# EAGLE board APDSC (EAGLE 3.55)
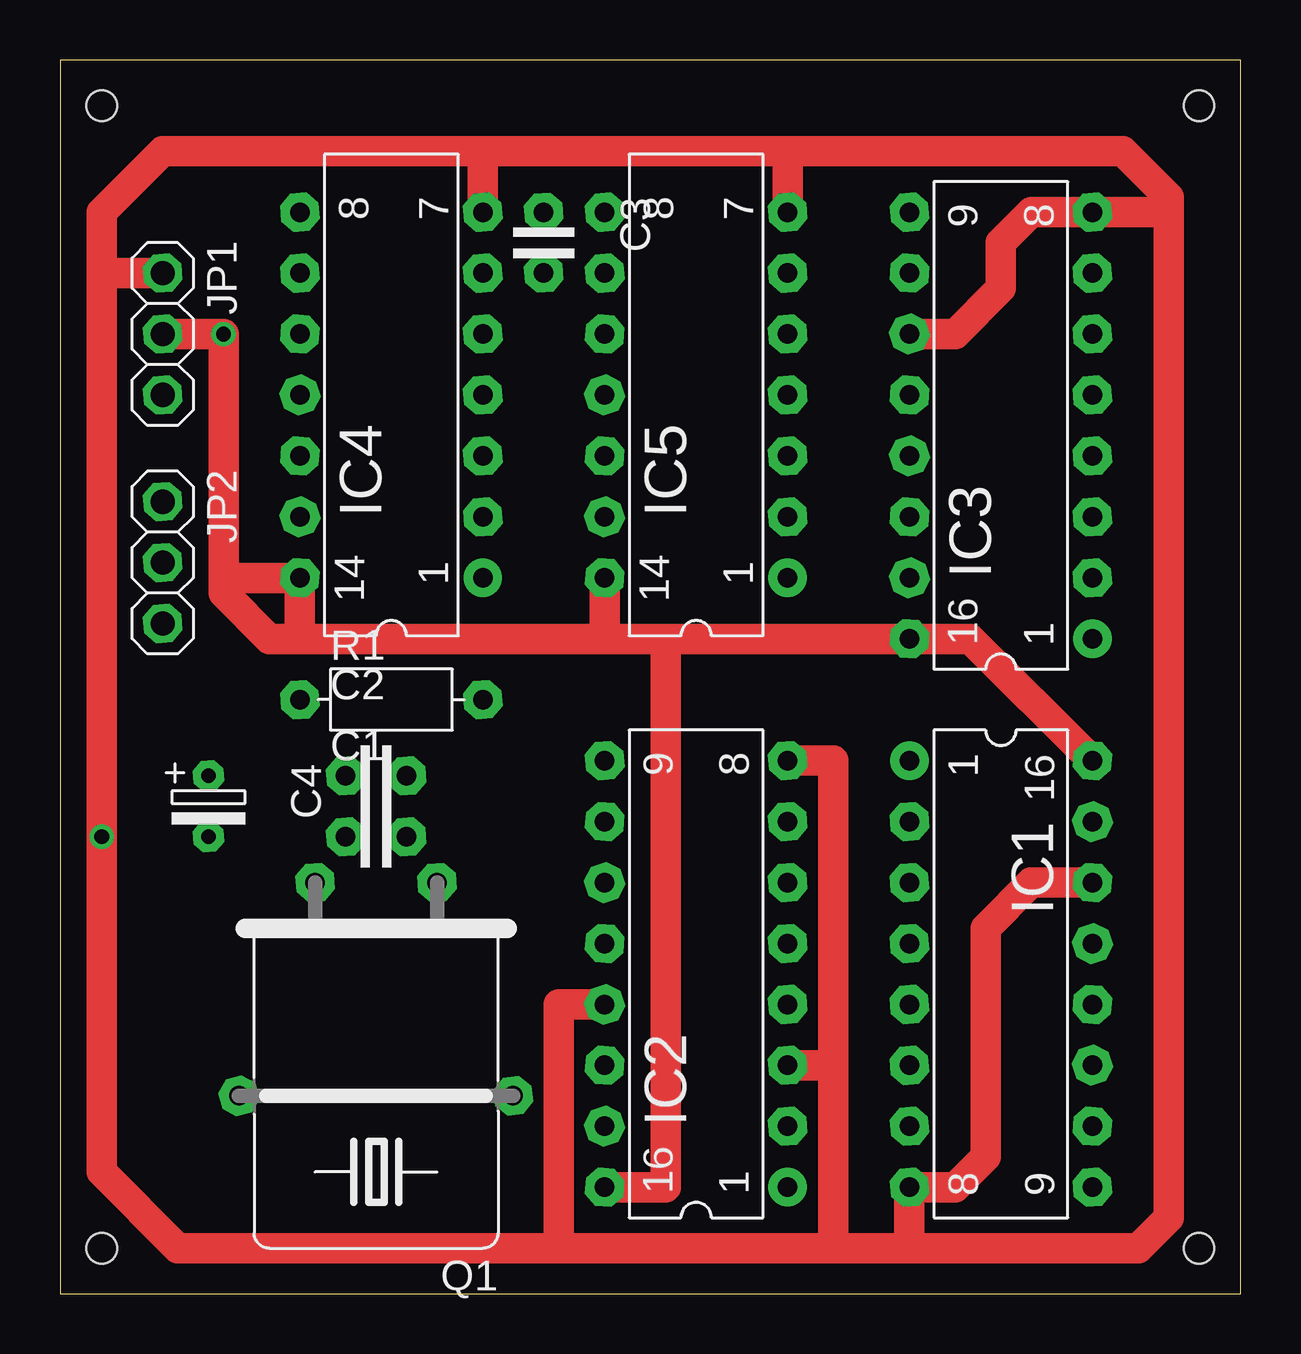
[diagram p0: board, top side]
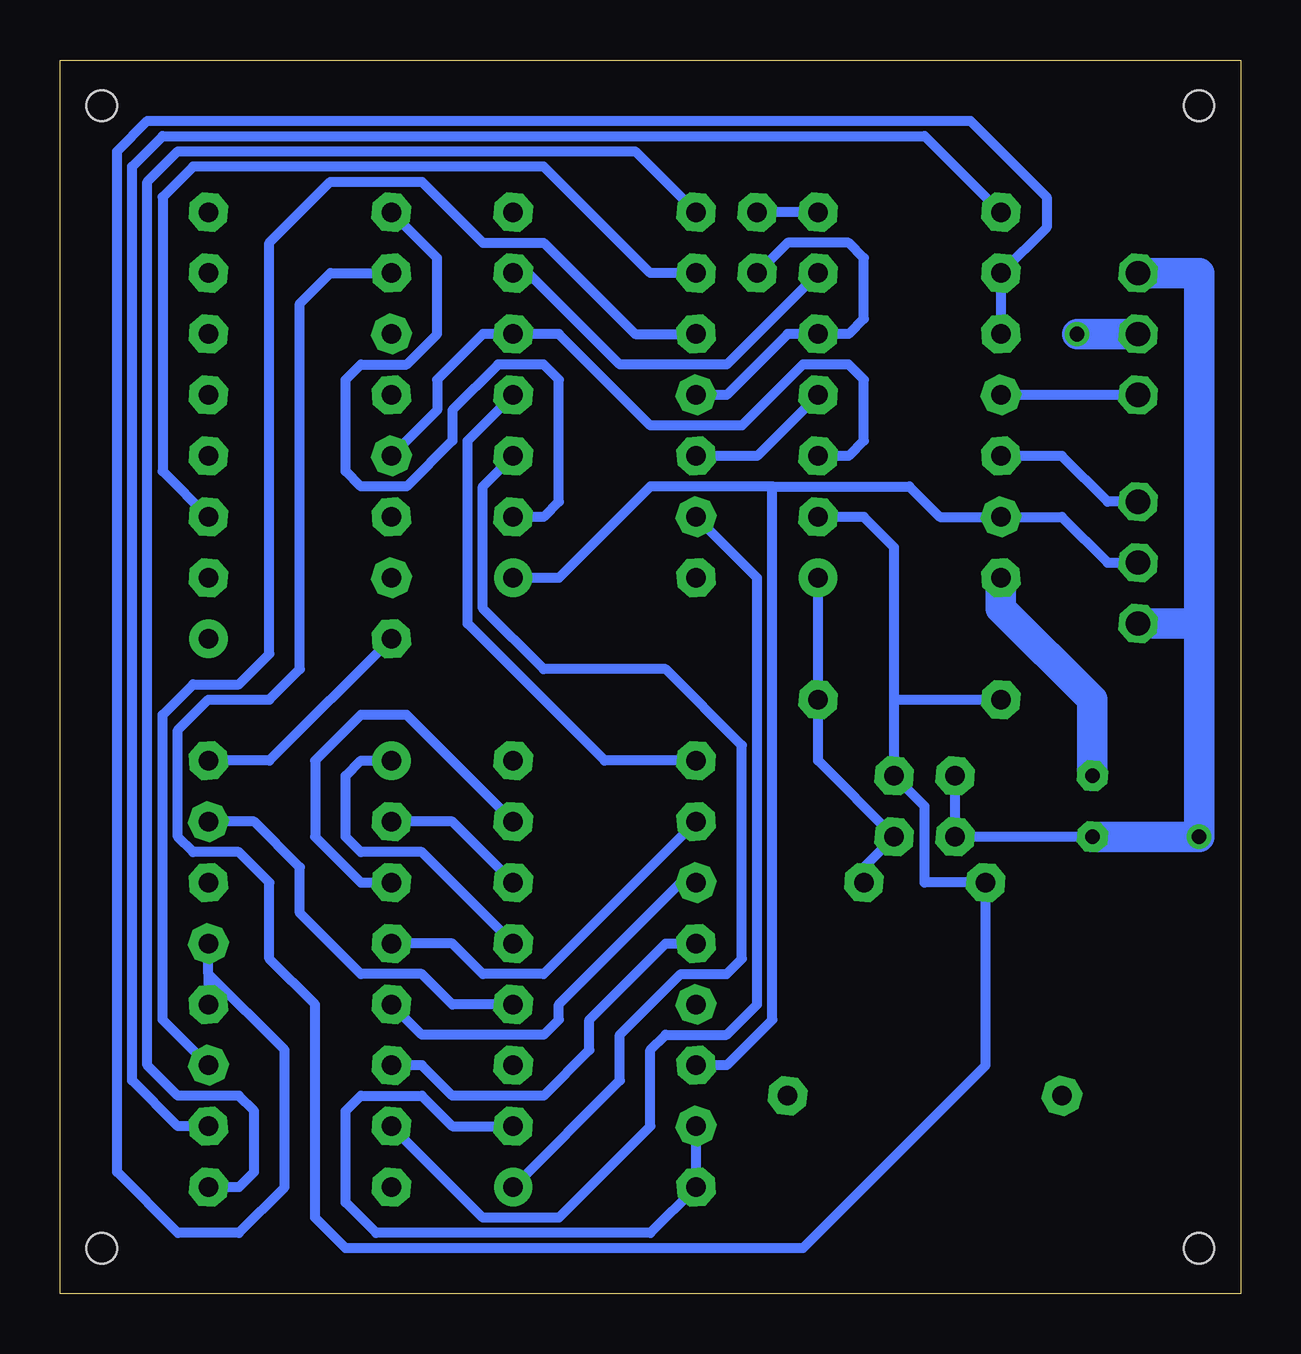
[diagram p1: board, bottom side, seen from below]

Size 49.2 x 51.42 mm. Coordinates in mm from the lower left corner, seen from the top.
Outline: 0,0 49.2,0 49.2,51.42 0,51.42 0,0
Copper layers used: Top, Bottom
Holes 1.27 mm at 1.74,1.9 1.74,49.53 47.46,49.53 47.46,1.9

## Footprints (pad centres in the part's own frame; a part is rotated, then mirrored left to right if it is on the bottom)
2,5 = drill 0.813 pad 1.6 octagon:  -1.27,0;  1.27,0
-2,5 = drill 0.61 pad 1.27 octagon:  -1.27,0;  1.27,0
L16 = drill 0.813 pad 1.6 round:  -8.89,-3.81 | drill 0.813 pad 1.6 octagon:  -6.35,-3.81;  -3.81,-3.81;  -1.27,-3.81;  1.27,-3.81;  3.81,-3.81;  6.35,-3.81;  8.89,-3.81;  8.89,3.81;  6.35,3.81;  3.81,3.81;  1.27,3.81;  -1.27,3.81;  -3.81,3.81;  -6.35,3.81;  -8.89,3.81
L14 = drill 0.813 pad 1.6 round:  -7.62,-3.81 | drill 0.813 pad 1.6 octagon:  -5.08,-3.81;  -2.54,-3.81;  0,-3.81;  2.54,-3.81;  5.08,-3.81;  7.62,-3.81;  7.62,3.81;  5.08,3.81;  2.54,3.81;  0,3.81;  -2.54,3.81;  -5.08,3.81;  -7.62,3.81
03 = drill 1.016 pad 1.6 octagon:  -2.54,0;  0,0;  2.54,0
18U-H = drill 0.813 pad 1.6 octagon:  -2.54,-5.08;  2.54,-5.08;  -5.715,3.81;  5.715,3.81
7,5 = drill 0.813 pad 1.6 octagon:  -3.81,0;  3.81,0

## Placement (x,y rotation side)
C1  22p  [2,5]  13.17,19.05 0 top
C2  22p  [2,5]  13.17,21.59 0 top
C3  1n  [2,5]  20.16,43.81 270 top
C4  10u  [-2,5]  6.18,20.31 270 top
IC1  74HC590  [L16]  39.21,13.33 270 top
IC2  HC40103  [L16]  26.5,13.33 90 top
IC3  HC4040  [L16]  39.21,36.19 90 top
IC4  HC4069  [L14]  13.8,37.46 90 top
IC5  HC4011  [L14]  26.5,37.46 90 top
JP1  PINHD-1X3  [03]  4.28,40 270 top
JP2  PINHD-1X3  [03]  4.28,30.48 270 top
Q1  4MHz  [18U-H]  13.17,12.06 180 top
R1  1M  [7,5]  13.8,24.76 0 top

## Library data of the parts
C1-C4 R1 = discrete
IC1-IC5 = HCF4xxxx
JP1 JP2 = pinhead
Q1 = quartz

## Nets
GND: C1. C2. C3. C4. IC1. IC2. IC3. IC4. IC5. JP1. JP2.
N$1: IC1. IC4.
N$2: IC1. IC4.
N$3: IC3. IC4. IC5.
N$4: IC1. IC5.
N$5: IC3. IC5.
N$8: IC1. IC5.
N$10: C1. IC4. Q1. R1.
N$12: C2. IC3. IC4. Q1. R1.
N$13: IC4. IC5.
N$14: IC1. IC2.
N$15: IC1. IC2.
N$16: IC1. IC2.
N$17: IC1. IC2.
N$18: IC1. IC2.
N$19: IC1. IC2.
N$20: IC1. IC2.
N$21: IC2. IC4. IC5. JP2.
N$23: IC2. IC5.
N$24: IC1. IC5.
N$25: C3. IC4. IC5.
N$27: IC4. IC5.
N$28: IC2. IC5.
N$29: IC3. IC5.
N$30: IC4. JP1.
N$31: IC4. JP2.
VDD: C4. IC1. IC2. IC3. IC4. IC5. JP1.

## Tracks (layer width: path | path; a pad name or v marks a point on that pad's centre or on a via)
GND  (via drill 0.61 pad 1.02)
  Top 1.27: 35.4,40 37.3,40 39.21,41.91 39.21,43.81 40.48,45.08 43.01,45.08 46.19,45.08 | 43.01,17.14 40.48,17.14 38.57,15.23 38.57,5.71 37.3,4.44 35.4,4.44 35.4,1.9 | 46.19,45.08 46.19,45.72 44.29,47.62 30.32,47.62 | 46.19,45.08 46.19,3.17 44.92,1.9 35.4,1.9 | 30.32,47.62 30.32,45.08 | 17.62,47.62 30.32,47.62 | 17.62,47.62 17.62,45.08 | 30.32,22.22 32.22,22.22 32.22,9.52 | 32.22,9.52 30.32,9.52 | 17.62,47.62 4.28,47.62 1.74,45.08 1.74,42.54 | 22.7,12.06 20.79,12.06 20.79,1.9 | 32.22,1.9 35.4,1.9 | 32.22,1.9 32.22,9.52 | 20.79,1.9 32.22,1.9 | 1.74,42.54 4.28,42.54 | 1.74,42.54 v1.74,19.05 1.74,5.07 4.91,1.9 20.79,1.9
  Bottom 0.406: 17.62,45.08 20.16,45.08 | 11.9,21.59 11.9,19.05 C4. 5.55,19.05
  Bottom 1.27: 4.28,42.54 1.74,42.54 1.74,27.94 | 1.74,27.94 JP2. | C4. v1.74,19.05 1.74,27.94
N$1
  Bottom 0.406: 9.99,40 9.99,42.54 8.09,44.44 8.09,45.72 11.27,48.89 45.55,48.89 46.82,47.62 46.82,5.07 44.29,2.54 41.74,2.54 39.84,4.44 39.84,10.16 43.01,13.33 | 43.01,13.33 43.01,12.06 | 43.01,13.33 43.01,14.6
N$2
  Bottom 0.406: 43.01,6.98 44.29,6.98 46.19,8.88 46.19,46.98 44.92,48.25 13.17,48.25 9.99,45.08
N$3
  Bottom 0.406: 17.62,34.92 16.34,34.92 15.71,35.55 15.71,38.09 16.34,38.73 18.25,38.73 20.79,36.19 24.6,36.19 28.41,40 30.32,40 31.59,40 33.49,38.09 33.49,36.83 35.4,34.92
N$4
  Bottom 0.406: 22.7,40 25.23,40 29.04,43.81 31.59,43.81 34.12,46.35 37.93,46.35 40.48,43.81 40.48,26.66 41.74,25.4 43.65,25.4 44.92,24.12 44.92,11.42 43.01,9.52
N$5
  Bottom 0.406: 43.01,32.38 44.92,34.28 44.92,45.72 43.65,46.98 29.04,46.98 24.6,42.54 22.7,42.54
N$8
  Bottom 0.406: 43.01,4.44 41.74,4.44 41.11,5.07 41.11,7.61 41.74,8.25 44.29,8.25 45.55,9.52 45.55,46.35 44.29,47.62 25.23,47.62 22.7,45.08
N$10
  Bottom 0.406: 17.62,29.84 R1. 17.62,22.22 C1. 15.71,17.77 15.71,17.14
N$12
  Bottom 0.406: 35.4,42.54 37.93,42.54 39.21,41.27 39.21,26.03 40.48,24.76 43.01,24.76 44.29,23.49 44.29,19.05 43.65,18.41 41.74,18.41 40.48,17.14 40.48,13.97 38.57,12.06 38.57,3.17 37.3,1.9 18.25,1.9 10.63,9.52 10.63,17.14 13.17,17.14 13.17,20.31 C2. 14.44,24.76 | 17.62,32.38 15.71,32.38 14.44,31.11 14.44,24.76 | 14.44,24.76 9.99,24.76
N$13
  Bottom 0.406: 17.62,37.46 20.16,34.92 22.7,34.92
N$14
  Bottom 0.406: 30.32,12.06 32.85,12.06 34.12,13.33 36.66,13.33 39.21,15.87 39.21,17.77 41.11,19.68 43.01,19.68
N$15
  Bottom 0.406: 35.4,22.22 36.66,22.22 37.3,21.59 37.3,19.05 36.66,18.41 34.12,18.41 30.32,14.6
N$16
  Bottom 0.406: 30.32,17.14 32.85,19.68 35.4,19.68
N$17
  Bottom 0.406: 30.32,19.68 34.76,24.12 36.66,24.12 38.57,22.22 38.57,19.05 36.66,17.14 35.4,17.14
N$18
  Bottom 0.406: 35.4,14.6 32.85,14.6 31.59,13.33 29.04,13.33 22.7,19.68
N$19
  Bottom 0.406: 35.4,12.06 34.12,10.79 29.04,10.79 28.41,11.42 28.41,12.06 23.33,17.14 22.7,17.14
N$20
  Bottom 0.406: 22.7,14.6 23.96,14.6 27.14,11.42 27.14,10.16 29.04,8.25 32.85,8.25 34.12,9.52 35.4,9.52
N$21
  Bottom 0.406: 22.7,9.52 21.42,9.52 19.52,11.42 19.52,33.65 | 19.52,33.65 24.6,33.65 28.41,29.84 30.32,29.84 | 19.52,33.65 13.8,33.65 12.53,32.38 9.99,32.38 7.45,32.38 5.55,30.48 4.28,30.48
N$23
  Bottom 0.406: 30.32,34.92 31.59,33.65 31.59,28.57 29.04,26.03 23.96,26.03 20.79,22.85 20.79,13.97 21.42,13.33 23.33,13.33 25.87,10.79 25.87,8.88 30.32,4.44
N$24
  Bottom 0.406: 35.4,6.98 31.59,3.17 28.41,3.17 24.6,6.98 24.6,10.16 23.96,10.79 21.42,10.79 20.16,12.06 20.16,29.84 22.7,32.38
N$25
  Bottom 0.406: 22.7,37.46 21.42,37.46 18.88,40 17.62,40 16.34,40 15.71,40.64 15.71,43.17 16.34,43.81 18.88,43.81 C3.
N$27
  Bottom 0.406: 30.32,42.54 29.68,42.54 25.87,38.73 21.42,38.73 17.62,42.54
N$28
  Bottom 0.406: 22.7,22.22 26.5,22.22 32.22,27.94 32.22,35.55 30.32,37.46
N$29
  Bottom 0.406: 30.32,32.38 29.04,32.38 28.41,33.02 28.41,38.09 29.04,38.73 30.95,38.73 32.85,36.83 32.85,35.55 34.76,33.65 36.66,33.65 37.3,34.28 37.3,38.09 36.66,38.73 34.76,38.73 33.49,40 33.49,43.17 35.4,45.08
N$30
  Bottom 0.406: JP1. 9.99,37.46
N$31
  Bottom 0.406: 4.28,33.02 5.55,33.02 7.45,34.92 9.99,34.92
VDD  (via drill 0.61 pad 1.02)
  Top 1.27: 4.28,40 v6.82,40 6.82,29.84 | 6.82,29.84 6.82,29.2 8.73,27.3 9.99,27.3 | IC1. 37.93,27.3 IC3. 25.23,27.3 | 22.7,27.3 IC5. | 22.7,27.3 9.99,27.3 | 25.23,27.3 22.7,27.3 | 25.23,27.3 25.23,4.44 IC2. | 6.82,29.84 IC4. 9.99,27.3
  Bottom 0.406: 30.32,6.98 32.85,6.98 34.12,8.25 36.66,8.25 37.3,7.61 37.3,3.8 36.03,2.54 24.6,2.54 IC2. 22.7,6.98 | IC1. 40.48,22.22 IC3.
  Bottom 1.27: v6.82,40 4.28,40 | IC4. 9.99,28.57 6.18,24.76 6.18,21.59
